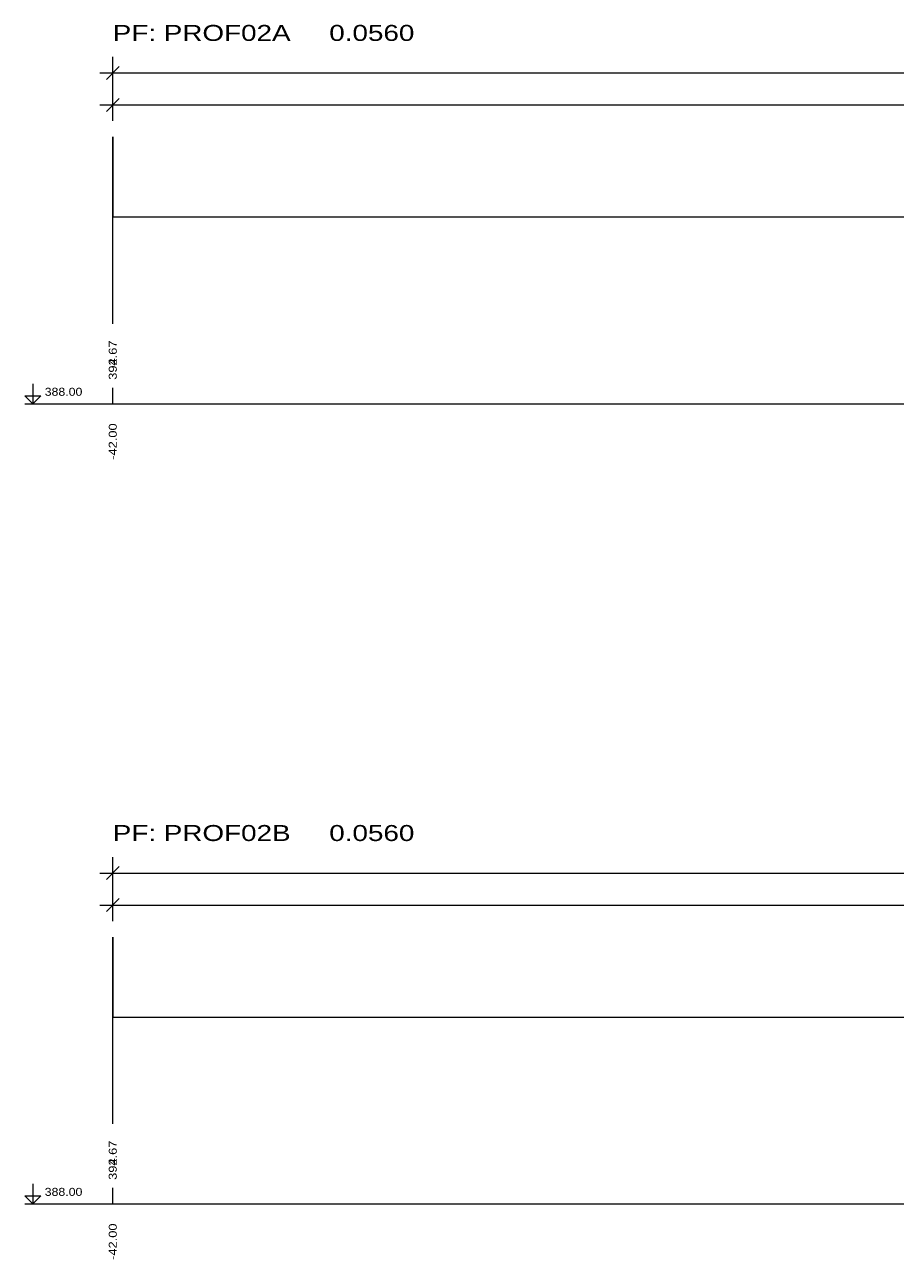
# Model space of a CAD drawing. Extents: x 7 to 442, y -393 to 441.
# Drawn here: x 257.44 to 279.19, y 354.81 to 385.68 of the extents above; entities that cross this region are included whole.
import ezdxf

# ---------------------------------------------------------------- set-up
doc = ezdxf.new("R2010")
doc.units = 0
doc.header["$LTSCALE"] = 0.08
doc.layers.add('7', color=7, linetype='Continuous', lineweight=13)

msp = doc.modelspace()

# ---------------------------------------------------------------- linework, layer by layer
at = {"layer": '7'}
for p, q in [((259.635, 383.27), (259.635, 384.87)), ((259.475, 384.31), (259.795, 384.63)), ((259.315, 384.47), (305.955, 384.47)), ((259.635, 383.35), (259.635, 383.99)), ((259.635, 383.35), (259.635, 383.99)), ((259.315, 383.67), (305.955, 383.67)), ((259.475, 383.51), (259.795, 383.83)), ((259.475, 383.51), (259.795, 383.83)), ((259.635, 378.2), (259.635, 382.87)), ((259.635, 378.2), (259.635, 380.87)), ((259.635, 376.2), (259.635, 376.6)), ((259.635, 376.2), (259.635, 376.6)), ((257.435, 376.2), (305.955, 376.2)), ((259.635, 363.27), (259.635, 364.87)), ((259.475, 364.31), (259.795, 364.63)), ((259.315, 364.47), (305.955, 364.47)), ((259.635, 363.35), (259.635, 363.99)), ((259.635, 363.35), (259.635, 363.99)), ((259.315, 363.67), (305.955, 363.67)), ((259.475, 363.51), (259.795, 363.83)), ((259.475, 363.51), (259.795, 363.83)), ((259.635, 358.2), (259.635, 362.87)), ((259.635, 358.2), (259.635, 360.87)), ((259.635, 356.2), (259.635, 356.6)), ((259.635, 356.2), (259.635, 356.6)), ((257.435, 356.2), (305.955, 356.2))]:
    msp.add_line(p, q, dxfattribs=at)
for points in [[(259.635, 382.87), (259.635, 380.87), (301.635, 380.87)], [(257.635, 376.7), (257.635, 376.2), (257.435, 376.4), (257.835, 376.4), (257.635, 376.2)], [(259.635, 362.87), (259.635, 360.87), (301.635, 360.87)], [(257.635, 356.7), (257.635, 356.2), (257.435, 356.4), (257.835, 356.4), (257.635, 356.2)]]:
    msp.add_lwpolyline(points, dxfattribs=at)

# ---------------------------------------------------------------- texts
for s, height, width, p in [('PF: PROF02A     0.0560', 0.4, 1.3, (259.635, 385.27)), ('388.00', 0.2, 1.15, (257.935, 376.4)), ('PF: PROF02B     0.0560', 0.4, 1.3, (259.635, 365.27)), ('388.00', 0.2, 1.15, (257.935, 356.4))]:
    msp.add_text(s, height=height, dxfattribs=dict(at, width=width)).set_placement(p)
at = {"layer": '7', "width": 1.2}
for s, p in [('394.67 ', (259.735, 376.8)), ('392.67 ', (259.735, 376.8)), ('-42.00 ', (259.735, 374.8)), ('-42.00 ', (259.735, 374.8)), ('394.67 ', (259.735, 356.8)), ('392.67 ', (259.735, 356.8)), ('-42.00 ', (259.735, 354.8)), ('-42.00 ', (259.735, 354.8))]:
    msp.add_text(s, height=0.2, rotation=90, dxfattribs=at).set_placement(p)

doc.saveas('drawing.dxf')
